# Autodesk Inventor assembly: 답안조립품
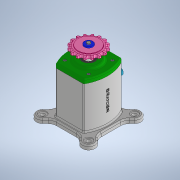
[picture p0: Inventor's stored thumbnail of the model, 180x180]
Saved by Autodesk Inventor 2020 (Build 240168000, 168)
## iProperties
Created: 2022-01
Part Number: 답안조립품
Document SubType Name: Assembly
Designer: user
Author: user
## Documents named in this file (13)
- C:\Users\user\Desktop\720117V1005\답안조립품.iam
- C:\Users\user\Desktop\720117V1005\베어링 6203.ipt
- C:\Users\user\Desktop\720117V1005\본체.ipt
- C:\Users\user\Desktop\720117V1005\볼트 M4 x 12.ipt
- C:\Users\user\Desktop\720117V1005\부시.ipt
- C:\Users\user\Desktop\720117V1005\스프로킷.ipt
- C:\Users\user\Desktop\720117V1005\슬라이더.ipt
- C:\Users\user\Desktop\720117V1005\오일 실 17 x 30 x 8.ipt
- C:\Users\user\Desktop\720117V1005\와셔 4 x 20.ipt
- C:\Users\user\Desktop\720117V1005\육각머리볼트 M4.ipt
- C:\Users\user\Desktop\720117V1005\커버.ipt
- C:\Users\user\Desktop\720117V1005\키 5 x 5.ipt
- C:\Users\user\Desktop\720117V1005\편심축.ipt
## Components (8 placed, 1 different names)
1. M4x0.7x12:1
2. M4x0.7x12:3
3. M4x0.7x12:4
4. M4x0.7x12:5
5. M4x0.7x12:2
6. M4x0.7x12:6
7. M4x0.7x12:7
8. M4x0.7x12:8
